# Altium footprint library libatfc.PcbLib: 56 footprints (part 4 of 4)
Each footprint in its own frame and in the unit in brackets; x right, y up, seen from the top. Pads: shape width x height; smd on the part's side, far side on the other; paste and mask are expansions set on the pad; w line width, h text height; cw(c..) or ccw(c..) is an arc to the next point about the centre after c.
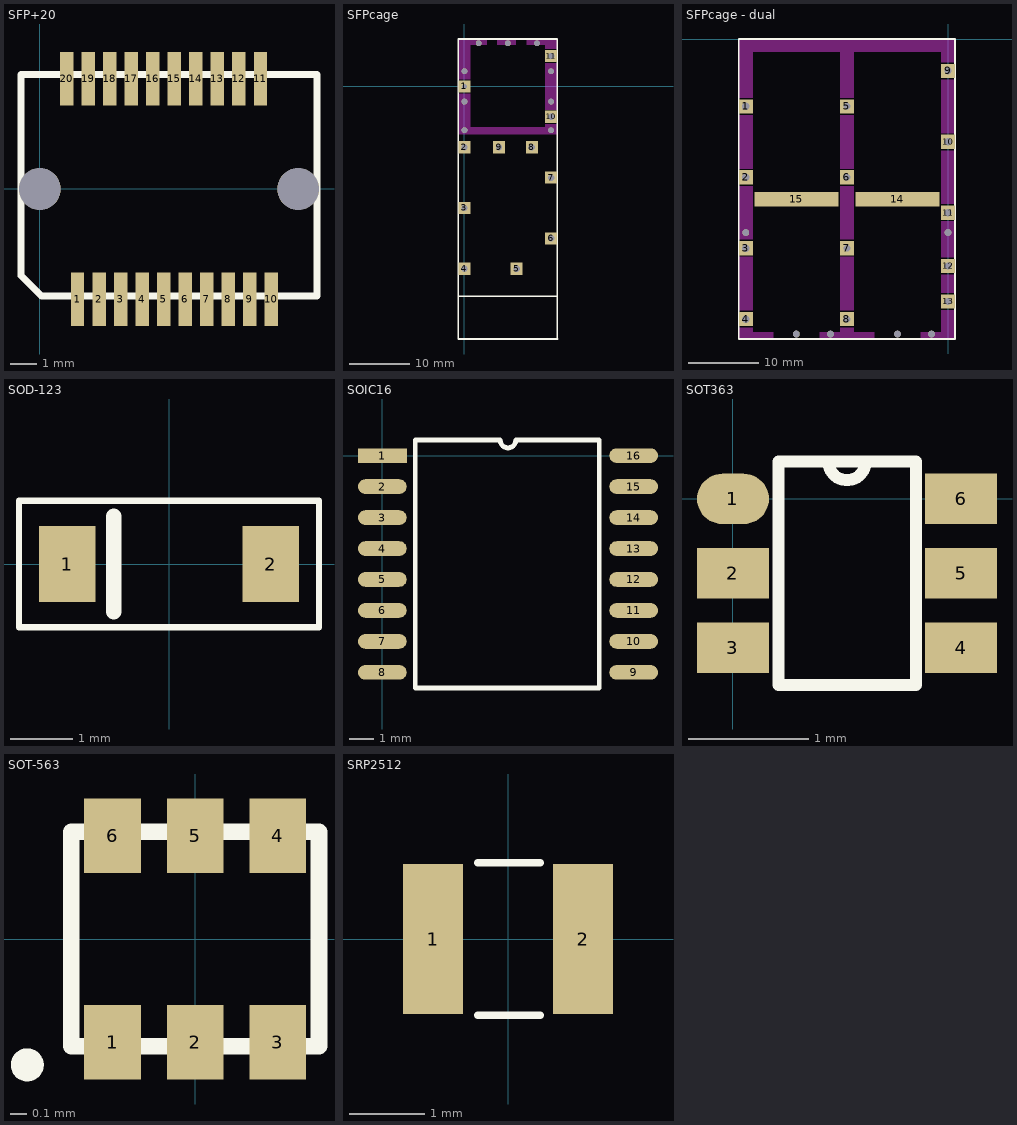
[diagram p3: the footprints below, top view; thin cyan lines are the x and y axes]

## SFP+20 [mm]
pads (22):
  rect 0.5x2 smd: 1(1.4,-4.1) 2(2.2,-4.1) 3(3,-4.1) 4(3.8,-4.1) 5(4.6,-4.1) 6(5.4,-4.1) 7(6.2,-4.1) 8(7,-4.1) 9(7.8,-4.1) 10(8.6,-4.1) 11(8.2,4.1) 12(7.4,4.1) 13(6.6,4.1) 14(5.8,4.1) 15(5,4.1) 16(4.2,4.1) 17(3.4,4.1) 18(2.6,4.1) 19(1.8,4.1) 20(1,4.1)
  round 1.55 hole 1.55 paste+0 mask+0: ""(0,0) ""(9.6,0)
Top Overlay:
  lines w0.254: -0.7,-3.223 -0.7,4.25 10.3,4.25 10.3,-3.98 0.057,-3.98 -0.7,-3.223
3D body "744410001.stp": height 5.37, standoff -0.9, extent -0.776,-4.457 10.224,4.693

## SFPcage [mm]
pads (20):
  round 0.95 hole 0.95: 0(0,-7.2) 0(0,-2.5) 0(0,2.5) 0(2.33,7.1) 0(7.13,7.1) 0(11.93,7.1) 0(14.25,-7.2) 0(14.25,-2.5) 0(14.25,2.5)
  rect 2x2 hole 0.85: 1(0,0)
  rect 2x2 hole 1.05: 2(0,-10) 3(0,-20) 4(0,-30) 5(8.58,-30) 6(14.25,-25) 7(14.25,-15) 8(11.08,-10) 9(5.68,-10) 10(14.25,-5) 11(14.25,5)
Top Layer keep-out:
  rectangle: 10.18,6.8 15.25,7.8
  rectangle: -1,6.8 3.68,7.8
  rectangle: 13.26,6.172 15.25,7.8
  rectangle: -1,-7.899 15.26,-6.7
  rectangle: 5.38,6.8 8.48,7.8
  rectangle: -1,-7.722 1,-1.168
  rectangle: 13.235,-3.861 15.225,3.861
  rectangle: 13.259,-7.2 15.249,-6.172
  rectangle: -1,1.168 1,7.8
Top Overlay:
  lines w0.254: -1,-34.5 15.25,-34.5 ; -1,-41.545 -0.991,-41.554 15.316,-41.554 15.25,-41.488 15.25,7.8 -1,7.8 -1,-41.545
3D body "c-2007194-1-b-3d.stp": height 10.62, standoff -2.97, extent -0.959,-41.58 15.336,7.22

## SFPcage - dual [mm]
pads (21):
  round 0.95 hole 0.95: 0(-28.5,-27.3) 0(-21.38,-41.6) 0(-16.58,-41.6) 0(-7.13,-41.6) 0(-2.33,-41.6) 0(0,-27.3)
  rect 2x2 hole 1.05: 1(-28.5,-9.5) 2(-28.5,-19.5) 3(-28.5,-29.5) 4(-28.5,-39.5) 9(0,-4.5) 10(0,-14.5) 11(0,-24.5)
  rect 2x2 hole 0.95: 5(-14.25,-9.5) 6(-14.25,-19.5) 7(-14.25,-29.5) 8(-14.25,-39.5) 12(0,-32) 13(0,-37)
  rect 11.8x2 smd: 14(-7.125,-22.6) 15(-21.375,-22.6)
Top Layer keep-out:
  rectangle: -15.25,-42.3 -13.25,-40.665
  rectangle: -15.25,-28.296 -13.25,-20.701
  rectangle: -15.25,-18.313 -13.25,-10.693
  rectangle: -15.25,-38.303 -13.25,-30.683
  rectangle: -15.25,-42.3 -10.37,-41.3
  rectangle: -3.88,-42.3 1,-41.3
  rectangle: -29.5,-42.3 -24.62,-41.3
  rectangle: -18.13,-42.3 -13.25,-41.3
  rectangle: -15.25,-8.306 -13.25,0
  rectangle: -1,-3.302 1,0
  rectangle: -29.5,-1.803 1.016,0
  rectangle: -29.5,-8.306 -27.5,0
  rectangle: -29.5,-38.303 -27.5,-30.683
  rectangle: -29.5,-18.313 -27.5,-10.693
  rectangle: -29.5,-28.296 -27.5,-20.701
  rectangle: -29.5,-42.3 -27.5,-40.665
  rectangle: -1,-13.31 1,-5.69
  rectangle: -1,-23.292 1,-15.697
  rectangle: -1,-30.81 1,-25.679
  rectangle: -1,-35.814 1,-33.198
  rectangle: -1,-42.3 1,-38.202
Top Overlay:
  lines w0.254: -29.5,-42.3 1,-42.3 1,0 -29.5,0 -29.5,-42.3
3D body "747540220.stp": height 10.47, standoff -3.11, extent -29.095,-42.367 1.053,6.658

## SOD-123 [mm]
pads (2):
  rect 0.91x1.22 smd: 1(-1.635,0) 2(1.635,0)
Top Overlay:
  lines w0.1: -2.413,-1.016 -0.889,-1.016 2.413,-1.016 2.413,1.016 -0.889,1.016 -2.413,1.016 -2.413,-1.016
  lines w0.254: -0.889,-0.762 -0.889,0.762
3D body: height 1.17, standoff 0, extent -1.27,-0.635 1.27,0.635
3D body: height 0.15, standoff 0, extent -1.651,-0.381 -1.27,0.381
3D body: height 0.15, standoff 0, extent 1.27,-0.381 1.651,0.381
3D body: height 1.18, standoff 1.17, extent -1.016,-0.635 -0.762,0.635

## SOIC16 [mm]
height 2.65
pads (16):
  rect 2x0.6 smd: 1(0,0)
  oval 2x0.6 smd: 2(0,-1.27) 3(0,-2.54) 4(0,-3.81) 5(0,-5.08) 6(0,-6.35) 7(0,-7.62) 8(0,-8.89) 9(10.3,-8.89) 10(10.3,-7.62) 11(10.3,-6.35) 12(10.3,-5.08) 13(10.3,-3.81) 14(10.3,-2.54) 15(10.3,-1.27) 16(10.3,0)
Top Overlay:
  lines w0.2: 1.346,-9.525 1.346,0.635 4.832,0.635 ccw(c5.15,0.635) 5.467,0.635 8.89,0.635 8.89,-9.525 1.346,-9.525
3D body: height 1, standoff 0, extent 1.346,-9.525 8.89,0.635

## SOT363 [mm]
pads (6):
  oval 0.6x0.42 smd: 1(0,0)
  rect 0.6x0.42 smd: 2(0,-0.62) 3(0,-1.24) 4(1.9,-1.24) 5(1.9,-0.62) 6(1.9,0)
Top Overlay:
  lines w0.1: 0.381,-1.55 1.524,-1.55 1.524,0.31 0.795,0.31 ccw(c0.95,0.31) 1.105,0.31 0.381,0.31 0.381,-0.639 0.381,-1.109 0.381,-1.55

## SOT-563 [mm]
pads (6):
  rect 0.343x0.45 smd: 1(-0.5,-0.625) 2(0,-0.625) 3(0.5,-0.625) 4(0.5,0.625) 5(0,0.625) 6(-0.5,0.625)
Top Overlay:
  circle w0.1: c-1.016,-0.762 r0.05
  lines w0.1: -0.75,-0.65 0.75,-0.65 0.75,0.65 -0.75,0.65 -0.75,-0.65
3D body: height 0.45, standoff 0, extent -0.762,-0.635 0.762,0.635

## SRP2512 [mm]
height 1.2
pads (2):
  rect 0.8x2 smd: 1(-1,0) 2(1,0)
Top Overlay:
  lines w0.1: -0.406,-1.016 0.432,-1.016 ; -0.406,1.016 0.432,1.016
